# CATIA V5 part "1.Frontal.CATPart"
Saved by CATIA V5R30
Part number: 1.Frontal
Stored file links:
  C:\Users\valen\Desktop\Estandar CubeSat - Programa AVES-20220531T050024Z-001\Estandar CubeSat - Programa AVES\3D - MODELS\CATIA\1.Frontal.CATPart

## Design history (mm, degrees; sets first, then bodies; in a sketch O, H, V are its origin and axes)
Body1 "Solid1" (main body)
  Solid1: solid without history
